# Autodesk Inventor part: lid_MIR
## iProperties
Shininess: 64.0
Length Units: 11272
Angle Units: 11279
Time Units: 11290
Mass Units: 11286
Length Display Precision: 3
Angle Display Precision: 2
Compacted: True
Part Number: lid_MIR
Document SubType Name: Modeling
Created: 2004-08
Designer: John Blackburn
Material: Default
Manufacturer: Standard
Standards Organization: Custom
Density: 0.0
Volumn: 0.0
Area: 0.0
PropertySet Name: Model Information
Control State: 0
Master: False
Checked Out: False
Author: John Blackburn
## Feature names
1. Derived Body1 [Tagging]
